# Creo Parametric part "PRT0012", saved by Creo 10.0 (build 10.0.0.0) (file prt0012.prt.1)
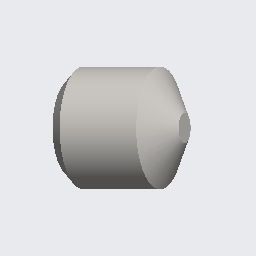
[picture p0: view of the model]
Units: millimeter Newton Second (mmNs); MM, TONNE, SECS

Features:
  1. coordinate system "61910404"
  2. imported feature "Import-ke ID 4"

Other named items: NOTE_0

Notes: 61910404

Surfaces: 9 plane, 4 cone, 2 cylinder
